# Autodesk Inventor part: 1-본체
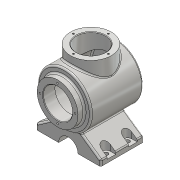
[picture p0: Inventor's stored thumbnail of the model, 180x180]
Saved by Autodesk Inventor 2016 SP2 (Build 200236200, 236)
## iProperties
Created: 2017-04
Part Number: 1-본체
Material: 알루미늄 6061
Document SubType Name: Modeling
Designer: H
Density: 2.7 g/cm^3
Appearance: 알루미늄 - 평지
Mass: 1664.47 g
Surface Area: 1066.85 cm^2
Volume: 616.47 cm^3
Author: H
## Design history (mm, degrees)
sketch "스케치2"
  geometry: L1 (-50, 0)-(-62, 0); L2 (-62, 0)-(-62, 38); L3 (-62, 38)-(-50, 38); L4 (-50, 38)-(-50, 0); L5 (-50, 0)-(46.336, 0); L6 (46.336, 0)-(46.336, 50); L7 (46.336, 50)-(-50, 50); L8 (-50, 50)-(-50, 0); L9 (46.336, 0)-(58, 0); A1 r 113 centre (-55, 0) between (58, 0) and (46.336, 50); 1 further point
  constraints: 18 end point, 4 parallel, 3 horizontal, 3 point on line, 2 perpendicular, 2 point on circle, 1 centre point
  dimensions: "d0" = 108 distance from line of L8 L9.end; "d1" = 12 distance of L2.end L3.end; "d2" = 76 diameter of L3 L1; "d3" = 100 diameter of L7 L5; "d4" = 113 radius of A1; "d5" = 50 distance from line of L4 point (0, 0)
revolve "회전1" sketch "스케치2" stored, may be unused: angle "d6" = 90 deg
sketch "스케치3"
  geometry: C1 r 38 at (0, 0); 1 further point
  constraints: 1 centre point, 1 coincident
  dimensions: "d7" = 76 diameter of C1
extrude "돌출1" join sketch "스케치3" distance "d8" = 65; taper "d9" = 0 deg
feature "쉘1" dims "d28" = 11, "d29" = 11, "d30" = 10
sketch "스케치7"
  geometry: L1 (-50, -50)-(-50, 50) reference; L2 (38, -82)-(-42, -82); L3 (-42, -82)-(-42, -72); L4 (-42, -72)-(38, -72); L5 (38, -72)-(38, -82); L6 (38, 65)-(-38, 65) reference; 1 further point
  constraints: 8 end point, 2 parallel, 1 horizontal, 1 perpendicular
  dimensions: "d12" = 8 distance between parallel lines of L1 L3; "d13" = 80 distance of L2.start L2.end; "d14" = 10 distance of L4.end L2.start; "d15" = 147 distance between parallel lines of L2 L6
extrude "돌출2" join sketch "스케치7" stored distance "d16" = 120; taper "d17" = 0 deg
sketch "스케치11"
  geometry: L1 (0, 10)-(38.416, 36.899); L2 (38.416, 36.899)-(81.584, 36.899); L3 (81.584, 36.899)-(120, 10); L4 (120, 10)-(0, 10); L5 (0, 0)-(0, 10) reference; A1 r 50 centre (60, 82) between (81.584, 36.899) and (38.416, 36.899) reference; 3 further points
  constraints: 8 end point, 2 coincident, 2 point on circle, 1 horizontal, 1 parallel
  dimensions: "d34" = 55 deg angle of L5 L1
extrude "돌출4" join sketch "스케치11" distance "d23" = 80; taper "d24" = 0 deg
node "작업 평면2"
sketch "스케치12"
  geometry: L1 (0, 0)-(120, 0) reference; C1 r 18 at (60, 0); 1 further point
  constraints: 1 centre point, 1 midpoint, 1 vertical alignment
  dimensions: "d25" = 18 radius of C1
extrude "돌출5" cut sketch "스케치12" stored distance "d26" = 80; taper "d27" = 0 deg
sketch "스케치15"
  geometry: 2 further points
  constraints: 1 coincident, 1 other
feature "엠보싱1" sketch "스케치15" dims "d0" = 108, "d1" = 12, "d2" = 76, "d3" = 100, "d4" = 113, "d5" = 50, "d12" = 8, "d13" = 80, "d14" = 10, "d15" = 147, "d31" = 0.5, "d32" = 0
sketch "스케치16"
  geometry: L1 (0, 0)-(0, 32.5)
  constraints: 2 end point, 1 vertical
  dimensions: "d35" = 32.5 distance of L1.start L1.end
hole "구멍1" sketch "스케치16" at (0, 32.5) diameter "d36" = 3.242; stored, may be unused: countersink angle "d40" = 90 deg, drill point angle "d42" = 118 deg; dims "d37" = 8, "d38" = 4, "d39" = 2, "d41" = 10
sketch "스케치17"
  geometry: L1 (0, 0)-(0, 32.5)
  constraints: 2 end point, 1 vertical
  dimensions: "d46" = 32.5 distance of L1.start L1.end
hole "구멍2" sketch "스케치17" at (0, 32.5) diameter "d47" = 3.242; stored, may be unused: countersink angle "d51" = 90 deg, drill point angle "d53" = 118 deg; dims "d48" = 8, "d49" = 4, "d50" = 2, "d52" = 10
node "작업 평면4"
sketch "스케치22"
  geometry: L1 (-60, -14)-(-50, -14); L2 (-50, -30)-(-60, -30); L3 (-60, -30)-(-60, -14); L4 (-60, -42)-(-60, 38) reference; L5 (-21.584, -42)-(-60, -42) reference; A1 r 8 centre (-50, -22) between (-50, -30) and (-50, -14); 1 further point
  constraints: 6 end point, 2 point on circle, 2 tangent, 1 centre point, 1 collinear, 1 horizontal, 1 parallel
  dimensions: "d80" = 20 distance from line of L5 A1.centre; "d81" = 10 distance from line of A1.centre L3; "d82" = 16 distance of L2.end L1.start
extrude "돌출7" cut sketch "스케치22" distance "d83" = 26; taper "d84" = 0 deg
hole "구멍4" diameter "d87" = 8; stored, may be unused: countersink angle "d91" = 90 deg, drill point angle "d93" = 118 deg; dims "d85" = 10, "d86" = 10, "d88" = 8, "d89" = 4, "d90" = 2, "d92" = 10
sketch "스케치23"
  geometry: L1 (-50, -22)-(50, -22); L2 (50, -22)-(50, 18); L3 (50, 18)-(-50, 18); L4 (-50, 18)-(-50, -22); C1 r 4 at (-50, -22) reference; 1 further point
  constraints: 8 end point, 2 parallel, 1 horizontal, 1 perpendicular
  dimensions: "d94" = 40 distance of L1.end L2.end; "d95" = 100 distance of L2.end L3.end
sketch "스케치24"
  geometry: L1 (-50, -22)-(-50, 18); C1 r 4 at (-50, -22) reference; 1 further point
  constraints: 2 end point, 1 vertical
  dimensions: "d102" = 40 distance of L1.start L1.end
fillet "모깎기1" dims "d106" = 3
chamfer "모따기1" distance "d107" = 1; stored, may be unused: second distance "d108" = 2, angle "d109" = 55 deg
fillet "모깎기2" dims "d110" = 3
fillet "모깎기3" dims "d111" = 3
fillet "모깎기4" dims "d112" = 3
fillet "모깎기5" dims "d113" = 3
fillet "모깎기6" dims "d114" = 3
fillet "모깎기7" dims "d115" = 3
node "솔리드1"
pattern_circular "원형 패턴1" dims angle "d44" = 360 deg
pattern_circular "원형 패턴2" dims angle "d55" = 360 deg
pattern_linear "직사각형 패턴2"
mirror "대칭1"
